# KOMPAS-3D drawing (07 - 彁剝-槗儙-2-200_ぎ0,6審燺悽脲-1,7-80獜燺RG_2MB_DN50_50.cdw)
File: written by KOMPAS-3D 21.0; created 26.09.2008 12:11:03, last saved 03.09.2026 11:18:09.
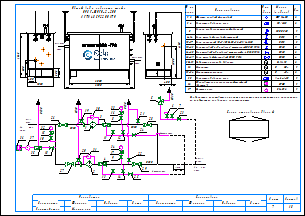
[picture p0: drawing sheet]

Sheets 1-2: A3, landscape

Document properties: Наименование: Макро:21; Автор: RaskoAdmin; Форматы листов документа: 2xA3; Полное имя файла: \\UR38nt01\Departments\КТО\КБ ПУРДГ\Заявки\Прайс-лист на типовые шкафы ГРПШ\ПРДГ_стандарт_20_03_2026\ПРДГ с RG_2MB\ПРДГ-ШУГО-2-200_до0,6МПа_Рвых-1,7-80кПа_RG_2MB_DN50_50.cdw

Title block, sheet 1: Наименование: Пункт учета газа / ПУГ-Ш-400-Р / ЛГТИ.485922.001ТУ; designation: ЛГТИ.03.4411141; sheet number: 1; Количество листов документа: 2; organisation: ООО "ЭЛЬСТЕР Газэлектроника"; Форматы листов документа: A3; stored path: C:\Рабочие документы\Компас\ПУГ\Схема.cdw; Разработал: Устинов; Проверил: Кошкин; Утвердил: Кошкин
Title block, sheet 2: sheet number: 2; stored path: D:\Рабочие документы\Заявки\ПУРДГ\ПУРДГ-ШУЭО-2-100-Р 4411220.cdw; designation, second copy: ЛГТИ.03.4411141-

Views: Вид 1, Вид 2
Referenced files: wcvoit.frw
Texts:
  Normal
  Вход
  газа
  PDI
  Выход
  Р=     кПа
  DN50
  DN20
  Импульс DN20
  ≥5DN
  HYSWLongFangSong
  Общий вид и габариты шкафа
  ПРДГ-ШУГО-2-200
  Выход газа
  Вход газа
  Р=       МПа
  logo-rasko-ge.png
  Схема открывания дверей
  Предприятие изготовитель может заменять комплектующие на аналогичные,
  не ухудшающие заявленных характеристик.
  № на
  схеме
  Усл.
  обозн.
  Марка
  (модель)
  Кол.
  Фильтр газовый фланцевый
  ФГ 16-50
  Регулятор давления газа
  RG/2MB
  Клапан предохранительный сбросной
  КПС DN20
  Кран шаровой газовый латунный
  DN15
  Кран кнопочный VE-РАСКО-НЗ-1,6-G1/2-М20
  Кран шаровой "под приварку" штуцерный DN20 PN16
  Кран шаровой "под приварку" штуцерный п/п DN20 PN16
  Кран шаровой фланцевый DN50 PN16
  Индикатор перепада давления
  Delta 15
  Манометр
  Манометр-напоромер
  0...     МПа
  0...     кПа
  Обогреватель газогорелочный шкафной
  (Эльтон")
  Счетчик газа
  Venio-A-15
  ОГШН
  BK-G1,6
  Должность
  Конструктор
  Фамилия
  Подпись
  Дата
  Согласовано
  Максимкин
  Лист
  Листов
  POLYLINE_STYLE_0.18_RGB_0_0_0
  POLYLINE_STYLE_0.50_RGB_0_0_0
  POLYLINE_STYLE_0.34_RGB_0_0_0
  PHANTOM_RGB_0_0_0_SC_1_THICK_0.18
  K5LT_THIN_RGB_0_0_0_THICK_0.18
  K5LT32769_RGB_0_0_0_THICK_0.18
  K5LT12_RGB_0_0_0_SC_1_THICK_0.18
  K5LT_DASHED_RGB_0_0_0_SC_1_THICK_0.18
  ACISOTGL_RGB_0_0_0_SC_0.8_THICK_0.25
  CONTINUOUS_RGB_0_127_31_THICK_0.3
  CONTINUOUS_RGB_0_0_255_THICK_0.35
  CONTINUOUS_RGB_255_0_0_THICK_0.35
  POLYLINE_STYLE_0.25_RGB_0_0_0
  CONTINUOUS_RGB_0_0_0_THICK_0.5
  POLYLINE_STYLE_0.35_RGB_0_0_255
  CONTINUOUS_RGB_0_0_0_THICK_0.4
  CONTINUOUS_RGB_0_0_0_THICK_0.35
  Без оформления
Dimensions and other numbers on the sheet: 1; 2; 3; 4; 5; 10; 27; 28; 29; 23; 8; 12; 19; 20; 21; 22; 25; 24; 30; 31; 15; 16; 26; 6; 7; 11; 14; 13; 33; 1000; 400; 1050; 500; 305; 2000; 4130; 1565; 32; 2300; 9; 17; 34; 18; 35; 36; 37; 1, 2; 3, 4; 6-14; 15-17; 18-23; 24-25; 26-29; 30-31; 33-34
